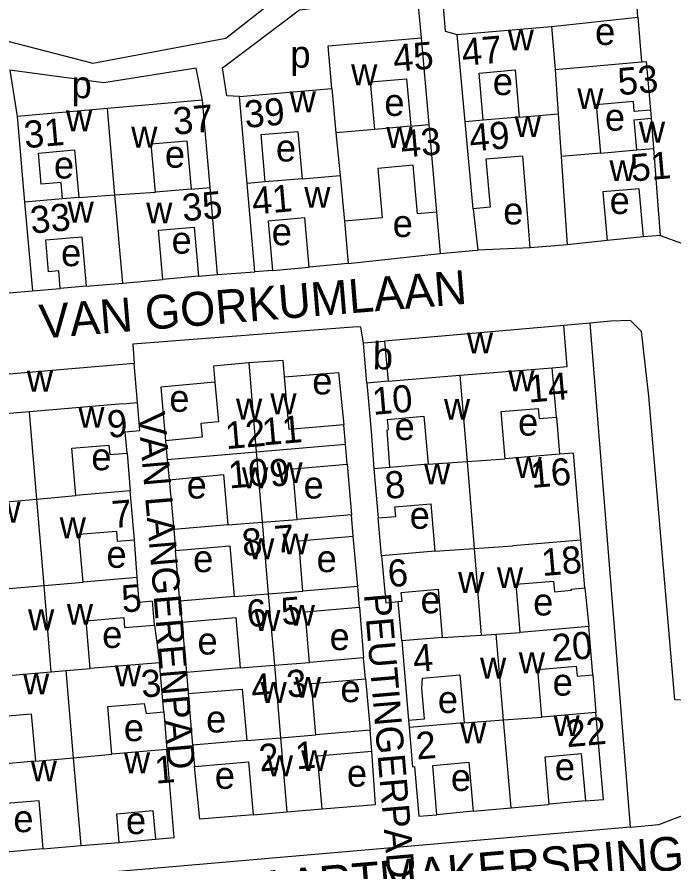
# Model space of a CAD drawing. Extents: x 163026 to 166241, y 382475 to 384501.
# Drawn here: x 164160.9 to 164257.7, y 383848 to 383972.8 of the extents above; entities that cross this region are included whole.
import ezdxf

# ---------------------------------------------------------------- set-up
doc = ezdxf.new("R2010")
doc.units = 0
for name, color, linetype in [('BLT_Basislijn', 7, 'Continuous'), ('BLT_Bebouwing', 7, 'Continuous'), ('BLT_Centroide', 7, 'Continuous'), ('BLT_Huisnummer', 7, 'Continuous'), ('BLT_Huisnummer_ tussenligend', 7, 'Continuous'), ('BLT_Onderverdeling_panden', 7, 'Continuous'), ('BLT_Straatnaam', 7, 'Continuous'), ('BLT_Straatnaam_verkleind', 7, 'Continuous')]:
    doc.layers.add(name, color=color, linetype=linetype)

msp = doc.modelspace()

# ---------------------------------------------------------------- linework, layer by layer
at = {"layer": 'BLT_Basislijn'}
for p, q in [((164239.72, 383971.41), (164252.46, 383972.77)), ((164252.46, 383972.77), (164253.02, 383966.17)), ((164254.31, 383959.06), (164254.41, 383957.87)), ((164228.18, 383944.52), (164228.86, 383938.43)), ((164222.79, 383944), (164223.3, 383937.94)), ((164253.29, 383940.36), (164247.94, 383939.82)), ((164236.6, 383938.74), (164228.86, 383938.43)), ((164209.74, 383936.43), (164223.3, 383937.94)), ((164198.61, 383935.44), (164204.01, 383935.92)), ((164187.71, 383934.56), (164182.45, 383934.08)), ((164190.52, 383934.81), (164196, 383935.22)), ((164157.59, 383931.93), (164163.21, 383932.4)), ((164171.15, 383933.09), (164167.33, 383932.76)), ((164245.42, 383927.67), (164241.53, 383927.31)), ((164251.4, 383853.34), (164245.42, 383927.67)), ((164240.47, 383913.79), (164240.93, 383908.33)), ((164177.17, 383908.49), (164177.63, 383902.92)), ((164209.63, 383906.84), (164210.26, 383899.39)), ((164183.36, 383904.57), (164184.06, 383897.22)), ((164214.69, 383893.35), (164214.18, 383898.93)), ((164211.19, 383888.83), (164210.52, 383896.25)), ((164178.66, 383890.13), (164178.25, 383895.7)), ((164184.96, 383886.68), (164184.33, 383894.12)), ((164244.65, 383888.61), (164245.23, 383882.92)), ((164217.68, 383880.79), (164217.15, 383886.6)), ((164211.45, 383885.78), (164212.04, 383878.3)), ((164185.23, 383883.57), (164185.94, 383876.15)), ((164181.23, 383883.14), (164181.95, 383877.59)), ((164212.31, 383875.2), (164212.99, 383867.65)), ((164245.85, 383875.8), (164246.29, 383870.25)), ((164186.2, 383873.03), (164186.83, 383865.43)), ((164182.58, 383870.33), (164183.02, 383864.79)), ((164218.64, 383869.11), (164218.74, 383868.01)), ((164244.74, 383857.2), (164239.39, 383856.75)), ((164228.19, 383855.7), (164222.85, 383855.18)), ((164176.01, 383851.1), (164181.35, 383851.57)), ((164164.76, 383850.14), (164159.37, 383849.67))]:
    msp.add_line(p, q, dxfattribs=at)
for points in [[(164178.9, 383982.68), (164164.74, 383980.75), (164159.75, 383977.45), (164158.88, 383971.12), (164159.06, 383970.07), (164159.61, 383969.24), (164172.13, 383965.98), (164191.71, 383969.68), (164198.58, 383975.05), (164199, 383975.87), (164189.34, 383987), (164188.39, 383986.77), (164180.9, 383982.95), (164178.9, 383982.68)], [(164252.46, 383972.77), (164252.29, 383974.98), (164246.82, 383976.94), (164243.2, 383978.71), (164235.77, 383984.8), (164234.5, 383984.86), (164223.54, 383977.53), (164224.08, 383970.7), (164225.81, 383970.2)], [(164193.74, 383961.05), (164191.89, 383961.15), (164191.26, 383965.32), (164202.57, 383973.86), (164219.93, 383976.08), (164220.54, 383969.72)], [(164188.27, 383960.53), (164187.37, 383965.26), (164173.73, 383963.11), (164159.88, 383964.97), (164160.96, 383958.14)], [(164255.75, 383940.57), (164262.33, 383938.23), (164268.4, 383932.62)], [(164223.3, 383937.94), (164228.13, 383938.37), (164228.86, 383938.43)], [(164212, 383924.75), (164211.63, 383927.07), (164211.09, 383927.1), (164178.04, 383924.55), (164178.24, 383921.72)], [(164251.4, 383853.34), (164255.54, 383853.71), (164259.43, 383855.23), (164261.59, 383857.49), (164262.61, 383859.23), (164263.28, 383861.2), (164262.52, 383872.04), (164257.9, 383872.09), (164254.07, 383916.87), (164253.02, 383926.4), (164251.37, 383928.04), (164248.48, 383927.94), (164245.42, 383927.67)], [(164200.39, 383919.73), (164208.34, 383920.36), (164209.13, 383912.65)], [(164190.13, 383918.93), (164182.15, 383918.19), (164182.84, 383910.32)], [(164205.92, 383856.04), (164213.77, 383856.67), (164213.25, 383864.56)], [(164195.75, 383855.18), (164187.88, 383854.52), (164187.09, 383862.3)], [(164251.4, 383853.34), (164131.66, 383842.96), (164128.09, 383843.2), (164126.4, 383844.11), (164124.84, 383846.13), (164124.12, 383848.94)]]:
    msp.add_lwpolyline(points, dxfattribs=at)
at = {"layer": 'BLT_Bebouwing'}
for p, q in [((164225.81, 383970.2), (164239.72, 383971.41)), ((164239.72, 383971.41), (164240.28, 383965.05)), ((164220.54, 383969.72), (164221.66, 383956.92)), ((164227, 383957.34), (164225.81, 383970.2)), ((164240.28, 383965.05), (164253.02, 383966.17)), ((164193.74, 383961.05), (164207.34, 383962.24)), ((164194.86, 383948.24), (164193.74, 383961.05)), ((164188.27, 383960.53), (164174.27, 383959.3)), ((164189.4, 383947.67), (164188.27, 383960.53)), ((164174.27, 383959.3), (164160.96, 383958.14)), ((164160.96, 383958.14), (164162.07, 383945.49)), ((164228.18, 383944.52), (164227, 383957.34)), ((164234.98, 383958.04), (164229.66, 383957.58)), ((164254.41, 383957.87), (164254.76, 383953.41)), ((164218.99, 383956.68), (164213.68, 383956.22)), ((164221.66, 383956.92), (164222.79, 383944)), ((164254.76, 383953.41), (164255.75, 383940.57)), ((164202.97, 383948.95), (164197.54, 383948.47)), ((164186.61, 383947.43), (164181.35, 383946.97)), ((164190.52, 383934.81), (164189.4, 383947.67)), ((164196, 383935.22), (164194.86, 383948.24)), ((164170.04, 383946.19), (164167.67, 383945.98)), ((164162.07, 383945.49), (164163.21, 383932.4)), ((164209.2, 383942.7), (164209.74, 383936.43)), ((164255.75, 383940.57), (164253.29, 383940.36)), ((164242.04, 383939.22), (164236.6, 383938.74)), ((164209.74, 383936.43), (164204.01, 383935.92)), ((164187.71, 383934.56), (164190.52, 383934.81)), ((164198.61, 383935.44), (164196, 383935.22)), ((164171.15, 383933.09), (164176.53, 383933.56)), ((164176.53, 383933.56), (164182.45, 383934.08)), ((164163.21, 383932.4), (164167.33, 383932.76)), ((164241.53, 383927.31), (164215.14, 383925.02)), ((164212, 383924.75), (164215.14, 383925.02)), ((164212.52, 383918.82), (164212, 383924.75)), ((164178.24, 383921.72), (164148.71, 383919.2)), ((164240.47, 383913.79), (164239.83, 383921.07)), ((164212.52, 383918.82), (164213.13, 383911.73)), ((164209.38, 383909.82), (164209.13, 383912.65)), ((164213.13, 383911.73), (164213.55, 383906.18)), ((164182.84, 383910.32), (164183.09, 383907.57)), ((164209.63, 383906.84), (164209.38, 383909.82)), ((164183.09, 383907.57), (164183.36, 383904.57)), ((164240.93, 383908.33), (164232.9, 383907.63)), ((164215.92, 383906.38), (164213.55, 383906.18)), ((164213.55, 383906.18), (164214.18, 383898.93)), ((164221.54, 383906.87), (164215.92, 383906.38)), ((164177.63, 383902.92), (164169.61, 383902.23)), ((164178.25, 383895.7), (164177.63, 383902.92)), ((164210.26, 383899.39), (164202.23, 383898.7)), ((164210.52, 383896.25), (164210.26, 383899.39)), ((164192.03, 383897.9), (164184.06, 383897.22)), ((164184.06, 383897.22), (164184.33, 383894.12)), ((164244.05, 383895.67), (164234.03, 383894.8)), ((164244.65, 383888.61), (164244.05, 383895.67)), ((164222.56, 383894.03), (164214.69, 383893.35)), ((164178.66, 383890.13), (164170.68, 383889.45)), ((164211.19, 383888.83), (164203.1, 383888.14)), ((164211.45, 383885.78), (164211.19, 383888.83)), ((164192.94, 383887.37), (164184.96, 383886.68)), ((164184.96, 383886.68), (164185.23, 383883.57)), ((164245.23, 383882.92), (164235.13, 383882.04)), ((164223.63, 383881.3), (164217.68, 383880.79)), ((164217.68, 383880.79), (164218.64, 383869.11)), ((164181.95, 383877.59), (164171.73, 383876.72)), ((164212.04, 383878.3), (164204.08, 383877.62)), ((164212.31, 383875.2), (164212.04, 383878.3)), ((164193.84, 383876.82), (164185.94, 383876.15)), ((164185.94, 383876.15), (164186.2, 383873.03)), ((164246.29, 383870.25), (164238.32, 383869.56)), ((164226.84, 383868.72), (164218.74, 383868.01)), ((164212.99, 383867.65), (164204.99, 383866.97)), ((164213.25, 383864.56), (164212.99, 383867.65)), ((164194.81, 383866.11), (164186.83, 383865.43)), ((164183.02, 383864.79), (164174.92, 383864.1)), ((164186.83, 383865.43), (164187.09, 383862.3)), ((164163.65, 383863.05), (164155.56, 383862.36)), ((164200.73, 383855.6), (164205.92, 383856.04)), ((164228.19, 383855.7), (164233.79, 383856.19)), ((164195.75, 383855.18), (164200.73, 383855.6)), ((164170.39, 383850.62), (164176.01, 383851.1)), ((164164.76, 383850.14), (164170.39, 383850.62))]:
    msp.add_line(p, q, dxfattribs=at)
for points in [[(164207.34, 383962.24), (164206.79, 383968.52), (164220.54, 383969.72)], [(164253.02, 383966.17), (164253.69, 383966.23), (164254.31, 383959.06)], [(164229.66, 383957.58), (164229.05, 383964.52), (164234.37, 383964.98), (164234.98, 383958.04)], [(164213.68, 383956.22), (164213.07, 383963.23), (164218.38, 383963.69), (164218.99, 383956.68)], [(164254.31, 383959.06), (164251.93, 383958.86), (164251.81, 383960.34), (164246.33, 383959.86), (164246.96, 383952.73)], [(164252.33, 383953.2), (164251.94, 383957.65), (164254.41, 383957.87)], [(164197.54, 383948.47), (164196.93, 383955.45), (164202.36, 383955.93), (164202.97, 383948.95)], [(164181.35, 383946.97), (164180.73, 383954.07), (164185.99, 383954.53), (164186.61, 383947.43)], [(164167.67, 383945.98), (164167.46, 383948.41), (164164.51, 383948.15), (164164.11, 383952.73), (164169.43, 383953.19), (164170.04, 383946.19)], [(164236.6, 383938.74), (164236.12, 383945.07), (164235.49, 383952.29), (164230.06, 383951.82), (164230.68, 383944.74), (164228.18, 383944.52)], [(164246.96, 383952.73), (164252.33, 383953.2)], [(164222.79, 383944), (164219.97, 383943.75), (164219.34, 383950.94), (164214.11, 383950.48), (164214.75, 383943.18), (164209.2, 383942.7)], [(164253.29, 383940.36), (164252.67, 383947.47), (164247.31, 383947), (164247.94, 383939.82)], [(164204.01, 383935.92), (164203.37, 383943.18), (164197.98, 383942.71), (164198.61, 383935.44)], [(164182.45, 383934.08), (164181.81, 383941.35), (164187.07, 383941.82), (164187.71, 383934.56)], [(164167.33, 383932.76), (164167.11, 383935.37), (164165.6, 383935.24), (164165.18, 383939.93), (164170.51, 383940.4), (164171.15, 383933.09)], [(164247.94, 383939.82), (164242.04, 383939.22)], [(164239.83, 383921.07), (164242.06, 383921.27), (164241.53, 383927.31)], [(164200.39, 383919.73), (164200.2, 383922.17), (164195.1, 383921.78)], [(164178.73, 383915.95), (164178.24, 383921.72)], [(164195.1, 383921.78), (164189.93, 383921.33), (164190.13, 383918.93)], [(164209.13, 383912.65), (164201.05, 383911.96), (164200.39, 383919.73)], [(164190.13, 383918.93), (164190.64, 383913.12), (164188.04, 383912.88), (164188.22, 383910.82), (164182.84, 383910.32)], [(164177.17, 383908.49), (164176.9, 383911.65), (164179.06, 383911.84), (164178.73, 383915.95)], [(164232.9, 383907.63), (164232.3, 383914.62), (164237.79, 383915.09), (164237.92, 383913.57), (164240.47, 383913.79)], [(164215.92, 383906.38), (164215.5, 383911.93), (164215.7, 383911.95), (164215.56, 383913.46), (164220.93, 383913.93), (164221.54, 383906.87)], [(164169.61, 383902.23), (164169.02, 383909.21), (164174.49, 383909.68), (164174.61, 383908.27), (164177.17, 383908.49)], [(164244.05, 383895.67), (164242.96, 383908.5), (164240.93, 383908.33)], [(164202.23, 383898.7), (164201.59, 383906.16), (164209.63, 383906.84)], [(164183.36, 383904.57), (164191.39, 383905.35), (164192.03, 383897.9)], [(164214.18, 383898.93), (164216.78, 383899.16), (164216.65, 383900.57), (164221.95, 383901.03), (164222.56, 383894.03)], [(164170.68, 383889.45), (164170.07, 383896.52), (164175.59, 383896.99), (164175.71, 383895.49), (164178.25, 383895.7)], [(164203.1, 383888.14), (164202.47, 383895.56), (164210.52, 383896.25)], [(164184.33, 383894.12), (164192.31, 383894.8), (164192.94, 383887.37)], [(164214.69, 383893.35), (164215.29, 383886.44), (164217.15, 383886.6)], [(164181.23, 383883.14), (164180.93, 383886.65), (164178.97, 383886.48), (164178.66, 383890.13)], [(164235.13, 383882.04), (164234.52, 383889.15), (164240.05, 383889.63), (164240.19, 383888.06), (164242.66, 383888.28), (164242.65, 383888.43), (164244.65, 383888.61)], [(164217.15, 383886.6), (164217.7, 383886.65), (164217.59, 383887.94), (164223.01, 383888.41), (164223.63, 383881.3)], [(164204.08, 383877.62), (164203.44, 383885.1), (164211.45, 383885.78)], [(164171.73, 383876.72), (164171.13, 383883.77), (164176.68, 383884.24), (164176.81, 383882.76), (164181.23, 383883.14)], [(164185.23, 383883.57), (164193.21, 383884.25), (164193.84, 383876.82)], [(164245.85, 383875.8), (164245.23, 383882.92)], [(164182.58, 383870.33), (164181.95, 383877.59)], [(164238.32, 383869.56), (164237.71, 383876.58), (164243.37, 383877.07), (164243.5, 383875.6), (164245.85, 383875.8)], [(164204.99, 383866.97), (164204.34, 383874.52), (164212.31, 383875.2)], [(164218.64, 383869.11), (164221.03, 383869.32), (164220.64, 383873.85), (164220.72, 383875.33), (164226.22, 383875.8), (164226.84, 383868.72)], [(164186.2, 383873.03), (164194.16, 383873.71), (164194.81, 383866.11)], [(164174.92, 383864.1), (164174.32, 383871.11), (164179.7, 383871.57), (164179.99, 383870.11), (164182.58, 383870.33)], [(164155.02, 383867.97), (164157.42, 383868.18), (164157.3, 383869.56), (164163.05, 383870.05), (164163.65, 383863.05)], [(164244.74, 383857.2), (164247.4, 383857.43), (164246.29, 383870.25)], [(164218.74, 383868.01), (164219.24, 383862.25), (164219.53, 383862.28), (164220.17, 383854.95), (164222.85, 383855.18)], [(164181.35, 383851.57), (164184.13, 383851.81), (164183.02, 383864.79)], [(164205.92, 383856.04), (164205.25, 383863.88), (164213.25, 383864.56)], [(164239.39, 383856.75), (164238.79, 383863.73), (164244.13, 383864.19), (164244.74, 383857.2)], [(164187.09, 383862.3), (164195.08, 383862.99), (164195.75, 383855.18)], [(164222.85, 383855.18), (164222.22, 383862.43), (164227.56, 383862.9), (164228.19, 383855.7)], [(164159.37, 383849.67), (164158.76, 383856.82), (164164.15, 383857.28), (164164.76, 383850.14)], [(164233.79, 383856.19), (164239.22, 383856.66), (164239.39, 383856.75)], [(164176.01, 383851.1), (164175.65, 383855.32), (164180.99, 383855.78), (164181.35, 383851.57)]]:
    msp.add_lwpolyline(points, dxfattribs=at)
at = {"layer": 'BLT_Onderverdeling_panden'}
for p, q in [((164240.28, 383965.05), (164240.73, 383958.54)), ((164207.34, 383962.24), (164207.96, 383955.72)), ((164175.39, 383946.56), (164174.27, 383959.3)), ((164234.98, 383958.04), (164240.73, 383958.54)), ((164240.73, 383958.54), (164241.16, 383952.22)), ((164229.66, 383957.58), (164227, 383957.34)), ((164213.68, 383956.22), (164207.96, 383955.72)), ((164218.99, 383956.68), (164221.66, 383956.92)), ((164207.96, 383955.72), (164208.56, 383949.43)), ((164252.33, 383953.2), (164254.76, 383953.41)), ((164246.96, 383952.73), (164241.16, 383952.22)), ((164241.16, 383952.22), (164242.04, 383939.22)), ((164197.54, 383948.47), (164194.86, 383948.24)), ((164202.97, 383948.95), (164208.56, 383949.43)), ((164208.56, 383949.43), (164209.2, 383942.7)), ((164186.61, 383947.43), (164189.4, 383947.67)), ((164167.67, 383945.98), (164162.07, 383945.49)), ((164170.04, 383946.19), (164175.39, 383946.56)), ((164175.39, 383946.56), (164181.35, 383946.97)), ((164176.53, 383933.56), (164175.39, 383946.56)), ((164215.14, 383925.02), (164215.66, 383919.09)), ((164195.1, 383921.78), (164196.2, 383908.69)), ((164226.24, 383919.96), (164239.83, 383921.07)), ((164215.66, 383919.09), (164226.24, 383919.96)), ((164226.24, 383919.96), (164227.28, 383907.25)), ((164215.66, 383919.09), (164212.52, 383918.82)), ((164162.81, 383914.58), (164149.21, 383913.42)), ((164176.54, 383915.76), (164162.81, 383914.58)), ((164163.88, 383901.72), (164162.81, 383914.58)), ((164196.2, 383908.69), (164209.38, 383909.82)), ((164183.09, 383907.57), (164196.2, 383908.69)), ((164196.2, 383908.69), (164197.09, 383898.3)), ((164221.54, 383906.87), (164227.28, 383907.25)), ((164227.28, 383907.25), (164232.9, 383907.63)), ((164227.28, 383907.25), (164228.34, 383894.42)), ((164163.88, 383901.72), (164169.61, 383902.23)), ((164158.16, 383901.21), (164163.88, 383901.72)), ((164164.93, 383888.95), (164163.88, 383901.72)), ((164197.09, 383898.3), (164202.23, 383898.7)), ((164192.03, 383897.9), (164197.09, 383898.3)), ((164197.09, 383898.3), (164197.99, 383887.75)), ((164228.34, 383894.42), (164234.03, 383894.8)), ((164222.56, 383894.03), (164228.34, 383894.42)), ((164228.34, 383894.42), (164229.38, 383881.67)), ((164159.21, 383888.46), (164164.93, 383888.95)), ((164164.93, 383888.95), (164170.68, 383889.45)), ((164165.98, 383876.24), (164164.93, 383888.95)), ((164192.94, 383887.37), (164197.99, 383887.75)), ((164197.99, 383887.75), (164203.1, 383888.14)), ((164197.99, 383887.75), (164198.89, 383877.22)), ((164223.63, 383881.3), (164229.38, 383881.67)), ((164229.38, 383881.67), (164231.57, 383881.82)), ((164231.57, 383881.82), (164235.13, 383882.04)), ((164232.67, 383869.14), (164231.57, 383881.82)), ((164193.84, 383876.82), (164198.89, 383877.22)), ((164198.89, 383877.22), (164204.08, 383877.62)), ((164198.89, 383877.22), (164199.8, 383866.53)), ((164160.24, 383875.77), (164165.98, 383876.24)), ((164165.98, 383876.24), (164168.18, 383876.42)), ((164168.18, 383876.42), (164171.73, 383876.72)), ((164169.28, 383863.57), (164168.18, 383876.42)), ((164226.84, 383868.72), (164232.67, 383869.14)), ((164232.67, 383869.14), (164238.32, 383869.56)), ((164233.79, 383856.19), (164232.67, 383869.14)), ((164194.81, 383866.11), (164199.8, 383866.53)), ((164199.8, 383866.53), (164204.99, 383866.97)), ((164199.8, 383866.53), (164200.73, 383855.6)), ((164163.65, 383863.05), (164169.28, 383863.57)), ((164169.28, 383863.57), (164174.92, 383864.1)), ((164170.39, 383850.62), (164169.28, 383863.57))]:
    msp.add_line(p, q, dxfattribs=at)
msp.add_lwpolyline([(164176.54, 383915.76), (164178.73, 383915.95)], dxfattribs=at)

# ---------------------------------------------------------------- texts
at = {"layer": 'BLT_Centroide'}
for s, p in [('w', (164233.27, 383967.86)), ('e', (164246.15, 383968.67)), ('p', (164201.24, 383965.32)), ('w', (164210.2, 383962.72)), ('p', (164168.99, 383960.82)), ('e', (164231.08, 383961.28)), ('w', (164243.53, 383959.22)), ('w', (164201.14, 383958.75)), ('e', (164215.09, 383958.21)), ('w', (164168.17, 383955.94)), ('e', (164247.6, 383956.03)), ('w', (164234.31, 383955.08)), ('w', (164252.61, 383954.27)), ('w', (164177.78, 383953.53)), ('w', (164215.38, 383953.48)), ('e', (164199.11, 383951.49)), ('e', (164182.75, 383950.57)), ('e', (164166.39, 383948.98)), ('w', (164248.27, 383948.59)), ('w', (164203.29, 383944.66)), ('e', (164248.3, 383943.75)), ('w', (164168.4, 383942.48)), ('w', (164179.99, 383942.37)), ('e', (164232.62, 383942.21)), ('e', (164216.32, 383940.36)), ('e', (164198.49, 383939.13)), ('e', (164183.73, 383937.9)), ('e', (164167.44, 383936.05)), ('w', (164227.26, 383923.19)), ('w', (164162.39, 383917.56)), ('e', (164204.47, 383917.14)), ('w', (164233.36, 383917.62)), ('e', (164183.4, 383914.58)), ('w', (164198.29, 383914.22)), ('w', (164193.23, 383913.44)), ('w', (164223.88, 383913.41)), ('w', (164169.98, 383912.23)), ('e', (164216.6, 383910.43)), ('e', (164234.8, 383911.07)), ('e', (164171.9, 383905.96)), ('w', (164199.18, 383904.06)), ('w', (164234.42, 383904.84)), ('w', (164194.11, 383903.31)), ('w', (164220.94, 383903.88)), ('e', (164185.95, 383901.8)), ('e', (164203.19, 383901.8)), ('w', (164157.61, 383898.25)), ('e', (164218.83, 383897.33)), ('w', (164167.24, 383895.94)), ('w', (164195.01, 383892.84)), ('w', (164200.06, 383893.56)), ('e', (164174.14, 383891.58)), ('e', (164186.91, 383890.94)), ('e', (164205.11, 383890.94)), ('w', (164225.97, 383887.88)), ('w', (164231.69, 383888.59)), ('e', (164220.43, 383884.87)), ('e', (164237.03, 383884.55)), ('w', (164168.29, 383883.19)), ('w', (164201, 383883.03)), ('w', (164162.58, 383882.38)), ('w', (164195.91, 383882.28)), ('e', (164173.5, 383879.76)), ('e', (164207.02, 383879.44)), ('e', (164187.55, 383878.8)), ('w', (164234.91, 383876.03)), ('w', (164175.38, 383874.11)), ('w', (164229.2, 383875.25)), ('w', (164161.84, 383872.92)), ('w', (164196.84, 383871.66)), ('w', (164201.91, 383872.41)), ('e', (164208.62, 383871.77)), ('e', (164239.9, 383872.73)), ('e', (164222.98, 383870.17)), ('e', (164188.82, 383867.3)), ('w', (164240.03, 383866.78)), ('e', (164176.69, 383866.02)), ('w', (164226.27, 383865.72)), ('w', (164202.83, 383861.62)), ('w', (164176.7, 383861.3)), ('w', (164197.77, 383860.84)), ('w', (164162.97, 383860.09)), ('e', (164209.58, 383859.31)), ('e', (164240.22, 383860.27)), ('e', (164190.1, 383858.99)), ('e', (164224.9, 383858.67)), ('e', (164160.41, 383852.6)), ('e', (164177.01, 383852.31))]:
    msp.add_text(s, height=4, dxfattribs=at).set_placement(p)
msp.add_text('b', height=4, rotation=359, dxfattribs=at).set_placement((164213.37, 383920.86))
at = {"layer": 'BLT_Huisnummer'}
for s, rotation, p in [('47', 5.0097, (164226.67, 383965.58)), ('45', 4.9958, (164216.56, 383964.69)), ('53', 5.0036, (164249.67, 383961.24)), ('39', 5.0089, (164194.63, 383956.43)), ('37', 4.9989, (164184.11, 383955.42)), ('31', 5.0051, (164162.14, 383953.43)), ('49', 4.9966, (164227.79, 383952.96)), ('43', 5.0057, (164217.67, 383952.04)), ('51', 5.0016, (164251.55, 383948.52)), ('35', 5.0088, (164185.44, 383942.66)), ('41', 5.0028, (164195.74, 383943.65)), ('33', 5.0082, (164163.06, 383940.85)), ('14', 4.9544, (164236.39, 383915.93)), ('10', 4.9545, (164213.46, 383914.12)), ('9', 4.8952, (164174.41, 383910.73)), ('12', 4.8848, (164191.8, 383909.07)), ('11', 4.8848, (164197.2, 383909.62)), ('18', 4.9666, (164238.41, 383890.35)), ('6', 4.9675, (164215.76, 383888.7)), ('5', 4.8839, (164176.51, 383884.97)), ('5', 4.8814, (164200.03, 383883.14)), ('6', 4.8824, (164194.97, 383882.81)), ('22', 4.9633, (164242.03, 383865.12)), ('2', 4.9651, (164219.91, 383863.3)), ('1', 4.8792, (164202.14, 383861.85)), ('2', 4.8865, (164196.75, 383861.53)), ('1', 4.8836, (164181.4, 383859.74))]:
    msp.add_text(s, height=4, rotation=rotation, dxfattribs=at).set_placement(p)
at = {"layer": 'BLT_Huisnummer_ tussenligend'}
for s, rotation, p in [('10', 4.8824, (164192.24, 383903.27)), ('9', 4.8814, (164198.33, 383903.51)), ('16', 4.9544, (164236.82, 383903.34)), ('8', 4.9675, (164215.34, 383901.72)), ('7', 4.8839, (164175.08, 383897.42)), ('8', 4.8824, (164194.27, 383893.28)), ('7', 4.8814, (164199.03, 383893.75)), ('20', 4.9666, (164239.96, 383877.74)), ('4', 4.9651, (164219.47, 383876.17)), ('3', 4.8836, (164179.39, 383872.43)), ('4', 4.8865, (164195.61, 383871.85)), ('3', 4.8792, (164200.84, 383872.43))]:
    msp.add_text(s, height=4, rotation=rotation, dxfattribs=at).set_placement(p)
at = {"layer": 'BLT_Straatnaam'}
for s, rotation, p in [('VAN GORKUMLAAN', 4.6741, (164164.45, 383925.37)), ('KAARTMAKERSRING', 4.8284, (164192.39, 383841.45))]:
    msp.add_text(s, height=5, rotation=rotation, dxfattribs=at).set_placement(p)
at = {"layer": 'BLT_Straatnaam_verkleind'}
for s, rotation, p in [('VAN LANGERENPAD', 274.8944, (164178.77, 383914.41)), ('PEUTINGERPAD', 274.8723, (164212.07, 383887.67))]:
    msp.add_text(s, height=4, rotation=rotation, dxfattribs=at).set_placement(p)

doc.saveas('drawing.dxf')
